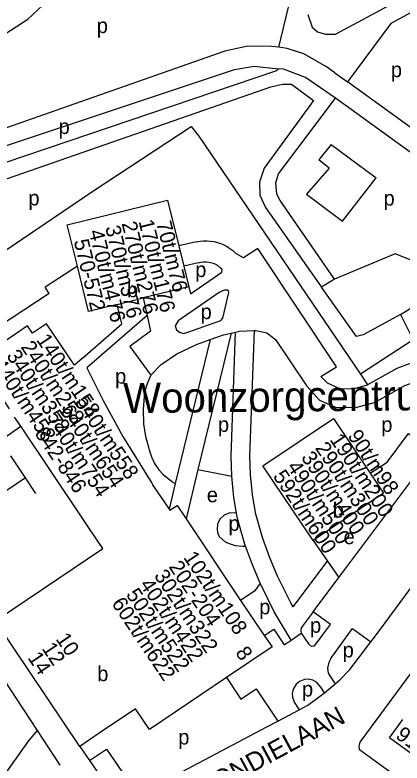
# Model space of a CAD drawing. Extents: x 159700 to 161346, y 381730 to 382922.
# Drawn here: x 159886.3 to 159989.4, y 382405.4 to 382604.4 of the extents above; entities that cross this region are included whole.
import ezdxf

# ---------------------------------------------------------------- set-up
doc = ezdxf.new("R2010")
doc.units = 0
for name, color, linetype in [('BLT_Basislijn', 7, 'Continuous'), ('BLT_Bebouwing', 7, 'Continuous'), ('BLT_Bebouwing_beschrifting', 7, 'Continuous'), ('BLT_Centroide', 7, 'Continuous'), ('BLT_Huisnummer', 7, 'Continuous'), ('BLT_Huisnummer_reeks', 7, 'Continuous'), ('BLT_Onderverdeling_panden', 7, 'Continuous'), ('BLT_Straatnaam', 7, 'Continuous')]:
    doc.layers.add(name, color=color, linetype=linetype)

msp = doc.modelspace()

# ---------------------------------------------------------------- linework, layer by layer
at = {"layer": 'BLT_Basislijn'}
for p, q in [((159968.25, 382645.34), (159956.51, 382595.83)), ((159889.8, 382603.33), (159895.13, 382608.32)), ((159971.51, 382589.02), (159974.86, 382586.62)), ((160050.2, 382532.12), (159974.86, 382586.62)), ((160008.29, 382555.7), (159971.62, 382582.3)), ((159970.47, 382569.96), (159967.21, 382565.85)), ((159970.47, 382569.96), (159982.43, 382561.13)), ((159969.93, 382563.65), (159967.21, 382565.85)), ((159969.93, 382563.65), (159963.89, 382556.76)), ((159973.53, 382549.57), (159982.43, 382561.13)), ((159963.89, 382556.76), (159973.53, 382549.57)), ((159934.69, 382544.04), (159929.93, 382543.04)), ((159935.14, 382538.47), (159931.29, 382537.58)), ((159902.95, 382537.63), (159894.34, 382531.97)), ((159940.34, 382537.8), (159940.9, 382537.26)), ((159971.42, 382534.12), (159967.9, 382532.02)), ((159895.41, 382530.34), (159894.34, 382531.97)), ((159895.41, 382530.34), (159876.85, 382518.14)), ((159943.85, 382519.77), (159945.07, 382520.05)), ((159938.29, 382518.05), (159929, 382479.76)), ((159943.85, 382519.77), (159935.05, 382483.51)), ((159978.31, 382508.84), (159980.17, 382506.05)), ((159870.68, 382483.2), (159887.87, 382494.99)), ((159984.88, 382442.73), (160020.14, 382490.75)), ((159889.11, 382481.28), (159885.22, 382487.11)), ((159972.5, 382454.72), (159997.49, 382488.09)), ((159935.05, 382483.51), (159931.86, 382470.34)), ((159935.05, 382483.51), (159944.06, 382481.68)), ((159889.11, 382481.28), (159865.26, 382465.24)), ((159891.9, 382477.11), (159889.11, 382481.28)), ((159929, 382479.76), (159927.34, 382472.94)), ((159965.7, 382464.59), (159969.5, 382459.07)), ((159960.4, 382446.91), (159969.5, 382459.07)), ((159969.5, 382459.07), (159972.5, 382454.72)), ((159965.7, 382445.65), (159972.5, 382454.72)), ((159970.29, 382442.25), (159965.7, 382445.65)), ((159982.03, 382438.87), (159984.88, 382442.73)), ((159968.21, 382439.4), (159970.29, 382442.25)), ((159970.36, 382433.2), (159976.18, 382441.17)), ((159976.18, 382441.17), (159981.06, 382437.6)), ((159959.87, 382438.11), (159962.55, 382439.92)), ((159968.68, 382424.07), (159971.54, 382426.49)), ((159886.63, 382422.6), (159892.22, 382414.08)), ((159919.07, 382396.91), (159953.34, 382415)), ((159892.22, 382414.08), (159898.27, 382404.83)), ((159906.19, 382406.1), (159914.24, 382394.31))]:
    msp.add_line(p, q, dxfattribs=at)
for points in [[(159964.29, 382604.57), (159965.4, 382601.24), (159966.84, 382599.94), (159968.96, 382599.3), (159971.64, 382599.3), (159987.33, 382607.75), (160001.12, 382614.9), (160129.6, 382682.99), (160132.19, 382684.55), (160132.13, 382685.82), (160132.99, 382686.55), (160192.92, 382718.42)], [(160158.27, 382680.77), (160148.41, 382687.83), (160147.14, 382687.99), (160105.06, 382665.27), (160004.9, 382612.26), (159986.37, 382602.17), (159974.86, 382586.62)], [(159855.56, 382583.35), (159870.61, 382590.99), (159889.8, 382603.33)], [(159956.51, 382595.83), (159954.65, 382596.09), (159948.3, 382596.16), (159942.23, 382594.8), (159870.56, 382569.67), (159864.9, 382569.86), (159863.78, 382571.02), (159859.81, 382575.17), (159855.56, 382583.35)], [(159971.51, 382589.02), (159969.26, 382590.67), (159963.22, 382594.12), (159958.8, 382595.52), (159956.51, 382595.83)], [(159861.3, 382557.55), (159862.69, 382558.97), (159870.07, 382564.27), (159877.61, 382567.55), (159944.77, 382589.9), (159949.96, 382590.83), (159956.45, 382590.15)], [(159956.45, 382590.15), (159955.96, 382589.59), (159861.3, 382557.55)], [(159971.62, 382582.3), (159963.68, 382587.84), (159957.85, 382590.06), (159956.45, 382590.15)], [(159856.25, 382551.21), (159954.46, 382585.29), (159957.51, 382585.99), (159959.92, 382586.03), (159965.76, 382581.67), (159952.66, 382563.64), (159951.39, 382559.98), (159951.55, 382556.48), (159952.98, 382553.2), (159967.9, 382532.02)], [(159971.42, 382534.12), (159956.89, 382555.08), (159956, 382556.73), (159955.79, 382559.79), (159956.51, 382562.2), (159971.62, 382582.3)], [(159829.63, 382505.14), (159907.05, 382557.53), (159933.2, 382574.77), (159935.27, 382572.16), (159978.31, 382508.84)], [(159934.69, 382544.04), (159935.6, 382544.23), (159936.53, 382544.33), (159937.46, 382544.35), (159938.39, 382544.29), (159939.31, 382544.15), (159940.21, 382543.94), (159941.1, 382543.65), (159941.95, 382543.28), (159942.77, 382542.84), (159943.55, 382542.33), (159944.29, 382541.76), (159944.97, 382541.12), (159945.16, 382540.93)], [(159969.45, 382506.53), (159967.78, 382508.23), (159971.89, 382510.84), (159950.95, 382542.26), (159947.16, 382539.81), (159945.16, 382540.93)], [(159995.39, 382537.49), (159994.88, 382537.93), (159987.49, 382540.85), (159971.42, 382534.12)], [(159935.14, 382538.47), (159935.84, 382538.64), (159936.55, 382538.73), (159937.27, 382538.74), (159937.99, 382538.67), (159938.69, 382538.52), (159939.37, 382538.3), (159940.03, 382537.99), (159940.34, 382537.8)], [(159932.63, 382532.14), (159933.08, 382530.28), (159941.39, 382535.97), (159941.46, 382536.68), (159940.9, 382537.26)], [(159988.92, 382524.76), (159992.88, 382527.16), (159998.53, 382534.9)], [(159988.92, 382524.76), (159978.99, 382519.31), (159977.19, 382518.91), (159967.9, 382532.02)], [(159921.54, 382524.47), (159922.4, 382520.27), (159916.91, 382516.21), (159922.47, 382508.64)], [(159988.92, 382524.76), (159992.34, 382517.96), (159978.31, 382508.84)], [(159944.06, 382481.68), (159944.05, 382481.81), (159943.86, 382487.07), (159945.07, 382520.05)], [(159945.07, 382520.05), (159946.14, 382520.29), (159950.09, 382520.46)], [(159960.4, 382446.91), (159959.75, 382447.99), (159956.25, 382455.15), (159954.18, 382459.95), (159952.21, 382465.43), (159950.47, 382471.6), (159949.58, 382476.74), (159949.04, 382482.15), (159948.86, 382487.06), (159950.09, 382520.46)], [(159950.09, 382520.46), (159950.41, 382520.47), (159953.4, 382519.88), (159955.69, 382518.11), (159964.01, 382505.65), (159967.39, 382501.98), (159971.63, 382500.05), (159977.03, 382499.98), (159982.02, 382501.36), (159990.07, 382505.82), (159992.32, 382506.64), (159995.08, 382506.83), (159997.44, 382506.45), (160006.53, 382500.16)], [(159922.47, 382508.64), (159925.23, 382511.44), (159929.44, 382514.28), (159934.69, 382516.77), (159938.29, 382518.05)], [(159938.29, 382518.05), (159941.82, 382519.31), (159943.85, 382519.77)], [(160009.01, 382504.81), (160004.1, 382508.08), (159999.33, 382510.83), (159995.6, 382511.88), (159991.27, 382511.58), (159987.99, 382510.38), (159980.17, 382506.05)], [(159922.47, 382508.64), (159921.58, 382506.57), (159920.81, 382504.1), (159920.44, 382499.45), (159920.57, 382495.63), (159921.11, 382492.31), (159922.2, 382488.19), (159922.66, 382486.86), (159923.51, 382485.06), (159924.67, 382483.43), (159925.74, 382482.12), (159928.33, 382480.08), (159929, 382479.76)], [(159969.45, 382506.53), (159972.75, 382505.04), (159976.38, 382504.99), (159980.17, 382506.05)], [(159980.9, 382482.49), (159985.4, 382485.45), (159991.03, 382493.1), (159997.49, 382488.09)], [(159945.34, 382471.89), (159944.63, 382476.06), (159944.06, 382481.68)], [(159945.34, 382471.89), (159943.55, 382471.96), (159942, 382471.37), (159940.9, 382470.27), (159940.25, 382468.96), (159940.15, 382467.53), (159940.36, 382466.41), (159940.81, 382465.56), (159942.24, 382464.24), (159943.37, 382463.76), (159944.96, 382463.26), (159946.94, 382463.05), (159947.73, 382463.12)], [(159947.73, 382463.12), (159947.45, 382463.9), (159945.58, 382470.5), (159945.34, 382471.89)], [(159951.62, 382453.26), (159949.53, 382458.11), (159947.73, 382463.12)], [(159951.62, 382453.26), (159950.21, 382451.21), (159946.36, 382448.66)], [(159959.87, 382438.11), (159955.36, 382445.59), (159951.7, 382453.07), (159951.62, 382453.26)], [(160001.68, 382391.75), (160001.38, 382391.97), (159978.05, 382408.94), (159977.91, 382409.89), (159978.23, 382410.9), (159994.7, 382433.33), (160002.19, 382443.55), (160008.66, 382451.78), (160010.48, 382453.23), (160012.45, 382453.12), (160013.98, 382452.17), (160034.05, 382437.41), (160034.48, 382437.1)], [(159866.86, 382451.98), (159879.58, 382433.33), (159886.63, 382422.6)], [(159965.7, 382445.65), (159962.53, 382441.38), (159962.41, 382440.5), (159962.55, 382439.92)], [(159952.7, 382439.33), (159955.22, 382440.97), (159958, 382436.84), (159959.87, 382438.11)], [(159962.55, 382439.92), (159964.42, 382437.13), (159964.89, 382436.7), (159965.33, 382436.52), (159965.86, 382436.58), (159966.44, 382437), (159968.21, 382439.4)], [(159981.06, 382437.6), (159982.03, 382438.87)], [(159971.54, 382426.49), (159972.84, 382427.52), (159975.46, 382430.27), (159977.8, 382433.33), (159981.06, 382437.6)], [(159970.36, 382433.2), (159969.84, 382432.13), (159969.55, 382430.64), (159969.72, 382429.31), (159970.11, 382428.58), (159971.54, 382426.49)], [(159942.61, 382428.12), (159946.44, 382422.38), (159950.52, 382425.13), (159956.31, 382416.57)], [(159968.68, 382424.07), (159967.76, 382425.59), (159966.56, 382426.93), (159965.63, 382427.41), (159964.45, 382427.69), (159963.36, 382427.61), (159962.1, 382427.07), (159961.17, 382426.34), (159960.38, 382425.08), (159960.07, 382423.9), (159960.21, 382422.88), (159960.61, 382421.62), (159962, 382419.58)], [(159962, 382419.58), (159964.27, 382420.78), (159968.68, 382424.07)], [(159956.31, 382416.57), (159962, 382419.58)], [(159953.34, 382415), (159956.31, 382416.57)], [(159892.22, 382414.08), (159889.81, 382411.2), (159864.9, 382376.1)], [(159903.58, 382409.83), (159906.19, 382406.1)], [(159906.19, 382406.1), (159910.7, 382409.1), (159919.07, 382396.91)]]:
    msp.add_lwpolyline(points, dxfattribs=at)
msp.add_lwpolyline([(159940.7, 382530.62), (159929.77, 382523.01), (159928.94, 382521.74), (159929.33, 382520.68), (159930.09, 382520.06), (159931.22, 382519.67), (159932.11, 382519.96), (159941.12, 382523.13), (159941.63, 382523.73), (159943.27, 382530.59), (159943.21, 382531.05), (159942.9, 382531.17), (159942.13, 382531.17), (159941.36, 382530.97)], close=True, dxfattribs=at)
at = {"layer": 'BLT_Bebouwing'}
for p, q in [((159929.93, 382543.04), (159931.29, 382537.58)), ((159921.54, 382524.47), (159905.43, 382510.57)), ((159887.87, 382494.99), (159886.24, 382497.41)), ((159896.31, 382482.43), (159887.87, 382494.99)), ((159903.89, 382471.16), (159896.31, 382482.43)), ((159929.47, 382473.91), (159931.86, 382470.34)), ((159905.84, 382468.25), (159903.89, 382471.16)), ((159931.86, 382470.34), (159946.36, 382448.66)), ((159909.71, 382462.49), (159905.84, 382468.25)), ((159881.11, 382443.26), (159909.71, 382462.49)), ((159903.58, 382409.83), (159881.11, 382443.26))]:
    msp.add_line(p, q, dxfattribs=at)
for points in [[(159902.95, 382537.63), (159900.25, 382548.57), (159926.93, 382555.16), (159929.93, 382543.04)], [(159913.54, 382527.43), (159905.93, 382525.55), (159902.95, 382537.63)], [(159931.29, 382537.58), (159932.63, 382532.14)], [(159932.63, 382532.14), (159920.42, 382529.14)], [(159920.42, 382529.14), (159921.54, 382524.47)], [(159904.28, 382513.08), (159914.82, 382522.23), (159913.54, 382527.43)], [(159904.28, 382513.08), (159902.18, 382511.24), (159894.72, 382522.27), (159891.01, 382519.78), (159889.72, 382521.69), (159880.26, 382515.34), (159881.53, 382513.43), (159878.42, 382511.34), (159878.09, 382511.13), (159880.4, 382507.71), (159879.67, 382507.2), (159884.76, 382499.65)], [(159905.43, 382510.57), (159909.77, 382501.88), (159915.01, 382492.26), (159922.74, 382479.85)], [(159965.7, 382464.59), (159952.34, 382484.47), (159971.11, 382497.08), (159980.9, 382482.49)], [(159980.9, 382482.49), (159984.46, 382477.19), (159965.7, 382464.59)], [(159922.74, 382479.85), (159922.96, 382479.49), (159922.9, 382479.45), (159927.34, 382472.94)], [(159927.34, 382472.94), (159927.56, 382472.63), (159929.47, 382473.91)], [(159946.36, 382448.66), (159952.7, 382439.33)], [(159952.7, 382439.33), (159954.77, 382436.29), (159942.61, 382428.12)], [(159942.61, 382428.12), (159922.13, 382414.35), (159918.42, 382419.82), (159908.78, 382413.33)], [(159995.81, 382412.49), (159992.27, 382407.6), (159986.04, 382412.12), (159989.58, 382417.01)], [(159908.78, 382413.33), (159903.58, 382409.83)]]:
    msp.add_lwpolyline(points, dxfattribs=at)
at = {"layer": 'BLT_Onderverdeling_panden'}
msp.add_line((159913.54, 382527.43), (159920.42, 382529.14), dxfattribs=at)

# ---------------------------------------------------------------- texts
at = {"layer": 'BLT_Bebouwing_beschrifting'}
msp.add_text('Woonzorgcentrum', height=8, rotation=0.5505, dxfattribs=at).set_placement((159915.19, 382498.5))
at = {"layer": 'BLT_Centroide'}
for s, p in [('p', (159908.1, 382599.62)), ('p', (159986.37, 382587.89)), ('p', (159897.95, 382572.76)), ('p', (159889.91, 382553.76)), ('p', (159984.43, 382553.71)), ('p', (159934.32, 382534.71)), ('b', (159916.13, 382529.32)), ('p', (159935.74, 382523.51)), ('p', (159912.99, 382506.34)), ('p', (159940.36, 382493.5)), ('p', (159983.83, 382493.5)), ('e', (159937.4, 382474.78)), ('b', (159970.91, 382470.72)), ('p', (159943.16, 382467.17)), ('e', (159973.8, 382463.62)), ('p', (159951.34, 382444.96)), ('p', (159964.87, 382440.05)), ('p', (159973.55, 382433.5)), ('b', (159908.23, 382427.17)), ('p', (159962.73, 382423.1)), ('p', (159929.78, 382410.31))]:
    msp.add_text(s, height=4, dxfattribs=at).set_placement(p)
at = {"layer": 'BLT_Huisnummer'}
msp.add_text('91', height=4, rotation=324.029, dxfattribs=at).set_placement((159987.4, 382412.2))
at = {"layer": 'BLT_Huisnummer_reeks'}
for s, rotation, p in [('370t/m376', 283.8286, (159910.33, 382547.94)), ('270t/m276', 283.8286, (159914.7, 382549.01)), ('170t/m176', 283.8286, (159919.21, 382549.53)), ('70t/m76', 283.8286, (159923.94, 382549.13)), ('470t/m476', 283.8286, (159905.96, 382546.86)), ('570-572', 283.8286, (159901.96, 382544.29)), ('140t/m158', 303.9128, (159891.9, 382517.98)), ('240t/m258', 303.9128, (159887.75, 382516.09)), ('340t/m358', 303.9128, (159883.93, 382513.73)), ('440t/m458', 303.9128, (159880.1, 382511.36)), ('540t/m558', 303.9128, (159902.1, 382501.44)), ('640t/m654', 303.9128, (159898.26, 382499.09)), ('740t/m754', 303.9128, (159894.44, 382496.72)), ('842-846', 303.9128, (159891.45, 382493.1)), ('190t/m200', 303.6386, (159970, 382491.45)), ('90t/m98', 303.6386, (159974.75, 382492.44)), ('290t/m300', 303.6386, (159966.1, 382489.2)), ('390t/m400', 303.6386, (159962.35, 382486.71)), ('490t/m500', 303.6386, (159958.6, 382484.21)), ('592t/m600', 303.6386, (159954.86, 382481.72)), ('102t/m108', 303.9128, (159931.03, 382460.11)), ('202-204', 303.9128, (159927.13, 382457.61)), ('302t/m322', 303.9128, (159923.22, 382455.24)), ('402t/m422', 303.9128, (159919.39, 382452.87)), ('502t/m522', 303.9128, (159915.75, 382450.22)), ('602t/m622', 303.9128, (159911.92, 382447.85)), ('10', 303.8745, (159897.06, 382438.41)), ('12', 303.8745, (159893.34, 382435.88)), ('8', 303.8745, (159944.87, 382434.75)), ('14', 303.8745, (159889.59, 382433.39))]:
    msp.add_text(s, height=4, rotation=rotation, dxfattribs=at).set_placement(p)
at = {"layer": 'BLT_Straatnaam'}
msp.add_text('MARIA VAN BOURGONDIELAAN', height=5, rotation=28.3112, dxfattribs=at).set_placement((159885.03, 382368.04))

doc.saveas('drawing.dxf')
